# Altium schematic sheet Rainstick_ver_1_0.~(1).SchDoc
size A4
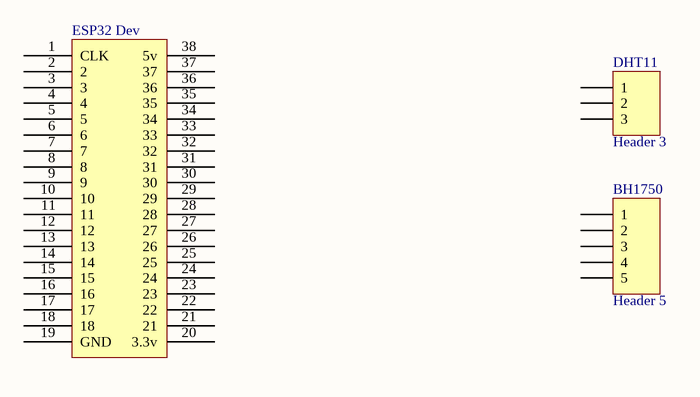
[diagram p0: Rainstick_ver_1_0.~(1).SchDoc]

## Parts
BH1750  Header 5  [HDR1X5]
DHT11  Header 3  [HDR1X3]
ESP32_Dev  (no value)  [PCBComponent_1]

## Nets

Not connected (* = marked no-connect by the designer): BH1750 1 2 3 4 5; DHT11 1 2 3; ESP32_Dev 1(CLK) 2 3 4 5 6 7 8 9 10 11 12 13 14 15 16 17 18 19(GND) 20(3.3v) 21 22 23 24 25 26 27 28 29 30 31 32 33 34 35 36 37 38(5v)

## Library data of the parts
BH1750 = Header 5: Header, 5-Pin
DHT11 = Header 3: Header, 3-Pin
ESP32_Dev = Component_1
